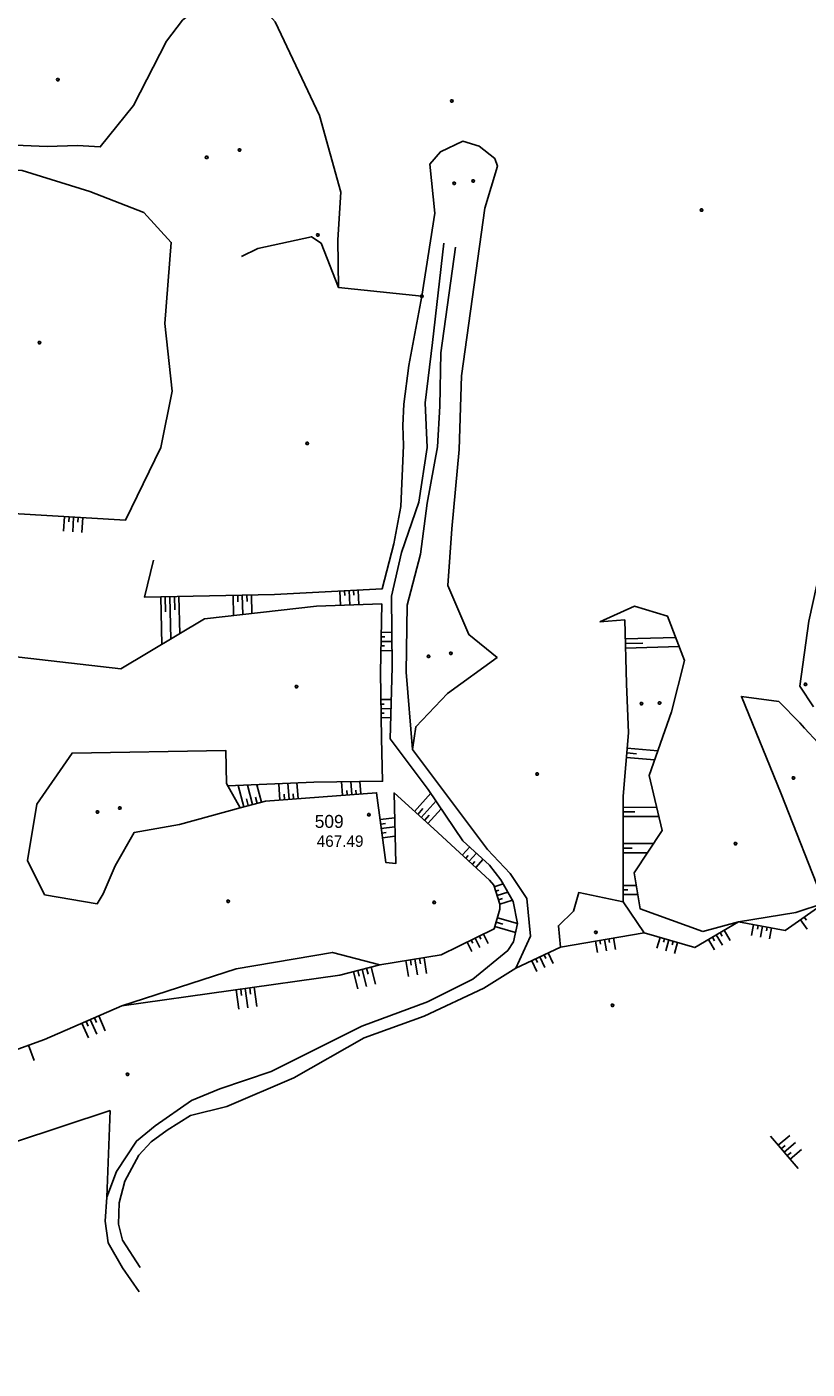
# Model space of a CAD drawing. Extents: x -664960 to -662754, y -993849 to -991145.
# Drawn here: x -664357.5 to -664152.5, y -993457.1 to -993104.4 of the extents above; entities that cross this region are included whole.
import ezdxf

# ---------------------------------------------------------------- set-up
doc = ezdxf.new("R2010")
doc.units = 0
for name, color, linetype in [('Vrstva 1', 7, 'Continuous'), ('Vrstva 12', 7, 'Continuous'), ('Vrstva 13', 7, 'Continuous'), ('Vrstva 18', 7, 'Continuous'), ('Vrstva 27', 7, 'Continuous'), ('Vrstva 63', 7, 'Continuous'), ('Vrstva 8', 7, 'Continuous')]:
    doc.layers.add(name, color=color, linetype=linetype)

msp = doc.modelspace()

# ---------------------------------------------------------------- linework, layer by layer
at = {"layer": 'Vrstva 12'}
msp.add_lwpolyline([(-664301.104, -993164.69), (-664296.848, -993162.65), (-664282.753, -993159.535), (-664280.216, -993161.227), (-664275.632, -993172.854), (-664253.73, -993175.159), (-664257.123, -993193.361), (-664258.44, -993203.55), (-664258.71, -993209.141), (-664258.56, -993214.4), (-664259.22, -993230.41), (-664261.06, -993240.18), (-664264.14, -993252.02), (-664292.45, -993253.54), (-664326.59, -993254.23), (-664324.275, -993244.488)], dxfattribs=at)
at = {"layer": 'Vrstva 13'}
for points in [[(-664349.185, -993117.942), (-664349.005, -993118.242), (-664349.185, -993118.542), (-664349.545, -993118.542), (-664349.725, -993118.242), (-664349.545, -993117.942), (-664349.185, -993117.942)], [(-664310.087, -993138.378), (-664309.907, -993138.678), (-664310.087, -993138.978), (-664310.447, -993138.978), (-664310.627, -993138.678), (-664310.447, -993138.378), (-664310.087, -993138.378)], [(-664301.437, -993136.432), (-664301.257, -993136.732), (-664301.437, -993137.032), (-664301.797, -993137.032), (-664301.977, -993136.732), (-664301.797, -993136.432), (-664301.437, -993136.432)], [(-664245.039, -993145.177), (-664244.859, -993145.477), (-664245.039, -993145.777), (-664245.399, -993145.777), (-664245.579, -993145.477), (-664245.399, -993145.177), (-664245.039, -993145.177)], [(-664240.048, -993144.566), (-664239.868, -993144.866), (-664240.048, -993145.166), (-664240.408, -993145.166), (-664240.588, -993144.866), (-664240.408, -993144.566), (-664240.048, -993144.566)], [(-664180.033, -993152.234), (-664179.853, -993152.534), (-664180.033, -993152.834), (-664180.393, -993152.834), (-664180.573, -993152.534), (-664180.393, -993152.234), (-664180.033, -993152.234)], [(-664354.029, -993187.034), (-664353.849, -993187.334), (-664354.029, -993187.634), (-664354.389, -993187.634), (-664354.569, -993187.334), (-664354.389, -993187.034), (-664354.029, -993187.034)], [(-664283.665, -993213.532), (-664283.485, -993213.832), (-664283.665, -993214.132), (-664284.025, -993214.132), (-664284.205, -993213.832), (-664284.025, -993213.532), (-664283.665, -993213.532)], [(-664251.766, -993269.477), (-664251.586, -993269.777), (-664251.766, -993270.077), (-664252.126, -993270.077), (-664252.306, -993269.777), (-664252.126, -993269.477), (-664251.766, -993269.477)], [(-664245.907, -993268.663), (-664245.727, -993268.963), (-664245.907, -993269.263), (-664246.267, -993269.263), (-664246.447, -993268.963), (-664246.267, -993268.663), (-664245.907, -993268.663)], [(-664286.486, -993277.411), (-664286.306, -993277.711), (-664286.486, -993278.011), (-664286.846, -993278.011), (-664287.026, -993277.711), (-664286.846, -993277.411), (-664286.486, -993277.411)], [(-664195.842, -993281.895), (-664195.662, -993282.195), (-664195.842, -993282.495), (-664196.202, -993282.495), (-664196.382, -993282.195), (-664196.202, -993281.895), (-664195.842, -993281.895)], [(-664191.054, -993281.734), (-664190.874, -993282.034), (-664191.054, -993282.334), (-664191.414, -993282.334), (-664191.594, -993282.034), (-664191.414, -993281.734), (-664191.054, -993281.734)], [(-664223.263, -993300.425), (-664223.083, -993300.725), (-664223.263, -993301.025), (-664223.623, -993301.025), (-664223.803, -993300.725), (-664223.623, -993300.425), (-664223.263, -993300.425)], [(-664155.894, -993301.408), (-664155.714, -993301.708), (-664155.894, -993302.008), (-664156.254, -993302.008), (-664156.434, -993301.708), (-664156.254, -993301.408), (-664155.894, -993301.408)], [(-664338.783, -993310.368), (-664338.603, -993310.668), (-664338.783, -993310.968), (-664339.143, -993310.968), (-664339.323, -993310.668), (-664339.143, -993310.368), (-664338.783, -993310.368)], [(-664332.924, -993309.351), (-664332.744, -993309.651), (-664332.924, -993309.951), (-664333.284, -993309.951), (-664333.464, -993309.651), (-664333.284, -993309.351), (-664332.924, -993309.351)], [(-664171.123, -993318.678), (-664170.943, -993318.978), (-664171.123, -993319.278), (-664171.483, -993319.278), (-664171.663, -993318.978), (-664171.483, -993318.678), (-664171.123, -993318.678)], [(-664304.443, -993333.814), (-664304.263, -993334.114), (-664304.443, -993334.414), (-664304.803, -993334.414), (-664304.983, -993334.114), (-664304.803, -993333.814), (-664304.443, -993333.814)], [(-664250.302, -993334.119), (-664250.122, -993334.419), (-664250.302, -993334.719), (-664250.662, -993334.719), (-664250.842, -993334.419), (-664250.662, -993334.119), (-664250.302, -993334.119)], [(-664207.812, -993341.974), (-664207.632, -993342.274), (-664207.812, -993342.574), (-664208.172, -993342.574), (-664208.352, -993342.274), (-664208.172, -993341.974), (-664207.812, -993341.974)], [(-664203.444, -993361.142), (-664203.264, -993361.442), (-664203.444, -993361.742), (-664203.804, -993361.742), (-664203.984, -993361.442), (-664203.804, -993361.142), (-664203.444, -993361.142)], [(-664330.878, -993379.271), (-664330.698, -993379.571), (-664330.878, -993379.871), (-664331.238, -993379.871), (-664331.418, -993379.571), (-664331.238, -993379.271), (-664330.878, -993379.271)]]:
    msp.add_lwpolyline(points, dxfattribs=at)
at = {"layer": 'Vrstva 18'}
for points in [[(-664245.69, -993123.56), (-664245.51, -993123.86), (-664245.69, -993124.16), (-664246.05, -993124.16), (-664246.23, -993123.86), (-664246.05, -993123.56), (-664245.69, -993123.56)], [(-664280.891, -993158.738), (-664280.711, -993159.038), (-664280.891, -993159.338), (-664281.251, -993159.338), (-664281.431, -993159.038), (-664281.251, -993158.738), (-664280.891, -993158.738)], [(-664253.55, -993174.859), (-664253.37, -993175.159), (-664253.55, -993175.459), (-664253.91, -993175.459), (-664254.09, -993175.159), (-664253.91, -993174.859), (-664253.55, -993174.859)]]:
    msp.add_lwpolyline(points, dxfattribs=at)
at = {"layer": 'Vrstva 27'}
for points in [[(-664247.94, -993161.23), (-664250.96, -993187.28), (-664252.81, -993203.17), (-664252.29, -993214.93), (-664254.49, -993229.29), (-664259.07, -993242.45), (-664261.72, -993253.99), (-664261.52, -993272.6), (-664262.05, -993291.42), (-664252.07, -993304.72), (-664242.91, -993318.25), (-664235.92, -993324.61), (-664232.93, -993328.5), (-664229.68, -993334.2), (-664228.56, -993340.01), (-664229.65, -993344.75)], [(-664229.01, -993351.74), (-664225.2, -993343.3), (-664226.12, -993333.39), (-664230.54, -993326.85), (-664236.51, -993320.52), (-664256.21, -993294.26), (-664257.8, -993273.94), (-664257.56, -993256.29), (-664254.09, -993242.89), (-664252.3, -993229.52), (-664249.58, -993214.77), (-664249, -993204.08), (-664248.69, -993190.01), (-664244.88, -993162.3)], [(-664314.24, -993386.46), (-664306.776, -993383.379), (-664293.287, -993378.845), (-664269.506, -993366.909), (-664252.229, -993360.577), (-664240.3, -993354.597), (-664231.144, -993347.069), (-664229.65, -993344.75)], [(-664229.01, -993351.74), (-664237.453, -993356.985), (-664253.09, -993364.277), (-664268.874, -993370.048), (-664287.316, -993380.536), (-664304.993, -993388.063), (-664314.496, -993390.431)], [(-664328.001, -993436.737), (-664332.398, -993430.456), (-664336.113, -993423.883), (-664336.904, -993418.153), (-664336.457, -993411.901), (-664333.964, -993405.119), (-664328.665, -993397.156), (-664323.816, -993393.158), (-664314.24, -993386.46)], [(-664314.496, -993390.431), (-664320.627, -993394.289), (-664324.839, -993397.33), (-664328.059, -993400.797), (-664331.791, -993407.686), (-664333.292, -993413.327), (-664333.438, -993418.976), (-664332.402, -993423.206), (-664327.759, -993430.373)]]:
    msp.add_lwpolyline(points, dxfattribs=at)
at = {"layer": 'Vrstva 63'}
for p, q in [((-664347.612, -993233.027), (-664347.842, -993236.924)), ((-664346.414, -993233.098), (-664346.491, -993234.395)), ((-664345.217, -993233.168), (-664345.446, -993237.065)), ((-664344.019, -993233.239), (-664344.095, -993234.537)), ((-664342.821, -993233.31), (-664343.05, -993237.207)), ((-664322.339, -993254.144), (-664322.086, -993266.678)), ((-664321.14, -993254.12), (-664321.06, -993258.066)), ((-664319.94, -993254.096), (-664319.714, -993265.262)), ((-664318.74, -993254.071), (-664318.669, -993257.562)), ((-664317.54, -993254.047), (-664317.342, -993263.847)), ((-664303.295, -993253.759), (-664303.188, -993259.073)), ((-664302.096, -993253.735), (-664302.061, -993255.466)), ((-664300.896, -993253.711), (-664300.793, -993258.797)), ((-664299.696, -993253.686), (-664299.663, -993255.342)), ((-664298.496, -993253.662), (-664298.398, -993258.521)), ((-664275.258, -993252.617), (-664275.057, -993256.362)), ((-664274.06, -993252.553), (-664273.993, -993253.808)), ((-664272.862, -993252.488), (-664272.658, -993256.286)), ((-664271.663, -993252.424), (-664271.595, -993253.697)), ((-664270.465, -993252.36), (-664270.258, -993256.21)), ((-664264.428, -993265.833), (-664261.592, -993265.896)), ((-664264.401, -993264.633), (-664263.47, -993264.654)), ((-664264.375, -993263.433), (-664261.618, -993263.495)), ((-664200.25, -993265.211), (-664187.006, -993264.841)), ((-664264.481, -993268.232), (-664261.566, -993268.297)), ((-664264.454, -993267.033), (-664263.497, -993267.054)), ((-664200.217, -993266.41), (-664195.667, -993266.283)), ((-664200.183, -993267.61), (-664186.102, -993267.217)), ((-664264.507, -993281.124), (-664261.759, -993281.084)), ((-664264.49, -993282.324), (-664263.592, -993282.311)), ((-664264.473, -993283.523), (-664261.827, -993283.485)), ((-664264.455, -993284.723), (-664263.591, -993284.711)), ((-664264.438, -993285.923), (-664261.894, -993285.886)), ((-664199.771, -993293.944), (-664191.737, -993294.596)), ((-664199.965, -993296.336), (-664192.569, -993296.937)), ((-664199.868, -993295.14), (-664197.299, -993295.349)), ((-664300.505, -993309.302), (-664301.958, -993303.718)), ((-664298.182, -993308.698), (-664299.506, -993303.608)), ((-664295.859, -993308.093), (-664297.055, -993303.499)), ((-664291.006, -993307.526), (-664291.329, -993303.243)), ((-664288.613, -993307.345), (-664288.931, -993303.136)), ((-664286.22, -993307.165), (-664286.532, -993303.029)), ((-664274.55, -993306.285), (-664274.819, -993302.73)), ((-664272.157, -993306.104), (-664272.414, -993302.696)), ((-664269.764, -993305.923), (-664270.01, -993302.663)), ((-664299.344, -993309), (-664299.806, -993307.223)), ((-664297.021, -993308.396), (-664297.44, -993306.783)), ((-664289.81, -993307.436), (-664289.916, -993306.022)), ((-664287.416, -993307.255), (-664287.521, -993305.866)), ((-664273.354, -993306.194), (-664273.441, -993305.035)), ((-664270.961, -993306.014), (-664271.044, -993304.903)), ((-664255.673, -993310.5), (-664251.384, -993305.733)), ((-664253.889, -993312.105), (-664249.998, -993307.781)), ((-664254.781, -993311.303), (-664253.419, -993309.789)), ((-664252.997, -993312.908), (-664251.767, -993311.542)), ((-664252.105, -993313.711), (-664248.612, -993309.828)), ((-664200.803, -993311.844), (-664191.47, -993311.867)), ((-664200.8, -993310.644), (-664197.788, -993310.651)), ((-664200.797, -993309.444), (-664192.038, -993309.466)), ((-664264.688, -993312.669), (-664260.862, -993312.169)), ((-664264.533, -993313.859), (-664263.3, -993313.698)), ((-664264.377, -993315.049), (-664260.799, -993314.581)), ((-664264.222, -993316.238), (-664263.072, -993316.088)), ((-664264.067, -993317.428), (-664260.736, -993316.993)), ((-664200.821, -993318.965), (-664192.884, -993318.985)), ((-664243.079, -993321.969), (-664241.142, -993319.859)), ((-664242.195, -993322.78), (-664241.549, -993322.076)), ((-664241.311, -993323.592), (-664239.367, -993321.474)), ((-664200.828, -993321.365), (-664194.447, -993321.381)), ((-664200.824, -993320.165), (-664198.44, -993320.171)), ((-664240.427, -993324.404), (-664239.779, -993323.697)), ((-664239.543, -993325.215), (-664237.592, -993323.089)), ((-664234.692, -993330.361), (-664232.315, -993329.578)), ((-664234.316, -993331.501), (-664233.448, -993331.215)), ((-664233.941, -993332.64), (-664231.102, -993331.706)), ((-664200.855, -993332.364), (-664196.972, -993332.374)), ((-664200.852, -993331.164), (-664199.626, -993331.167)), ((-664200.849, -993329.964), (-664197.368, -993329.973)), ((-664233.565, -993333.78), (-664232.543, -993333.444)), ((-664233.19, -993334.92), (-664229.889, -993333.833)), ((-664195.34, -993342.39), (-664200.86, -993334.24)), ((-664234.208, -993339.641), (-664232.417, -993340.154)), ((-664233.878, -993338.488), (-664228.56, -993340.01)), ((-664154.227, -993338.992), (-664152.511, -993341.431)), ((-664153.245, -993338.302), (-664152.674, -993339.114)), ((-664238.592, -993343.284), (-664238.192, -993344.093)), ((-664237.516, -993342.752), (-664236.316, -993345.181)), ((-664234.538, -993340.795), (-664229.099, -993342.352)), ((-664191.117, -993343.622), (-664191.946, -993346.465)), ((-664177.386, -993343.577), (-664176.85, -993344.484)), ((-664176.353, -993342.966), (-664174.742, -993345.688)), ((-664175.321, -993342.355), (-664174.784, -993343.261)), ((-664174.288, -993341.744), (-664172.677, -993344.465)), ((-664166.545, -993340.231), (-664167.092, -993343.131)), ((-664165.366, -993340.454), (-664165.548, -993341.419)), ((-664164.187, -993340.676), (-664164.733, -993343.575)), ((-664163.008, -993340.898), (-664163.189, -993341.864)), ((-664161.828, -993341.12), (-664162.375, -993344.02)), ((-664241.819, -993344.879), (-664240.619, -993347.308)), ((-664240.744, -993344.347), (-664240.344, -993345.156)), ((-664239.668, -993343.815), (-664238.467, -993346.245)), ((-664208.117, -993344.582), (-664207.602, -993347.581)), ((-664206.934, -993344.379), (-664206.763, -993345.378)), ((-664205.751, -993344.177), (-664205.237, -993347.175)), ((-664204.569, -993343.974), (-664204.397, -993344.972)), ((-664203.386, -993343.771), (-664202.871, -993346.769)), ((-664189.965, -993343.958), (-664190.241, -993344.905)), ((-664188.813, -993344.294), (-664189.642, -993347.137)), ((-664187.661, -993344.63), (-664187.937, -993345.577)), ((-664186.509, -993344.966), (-664187.338, -993347.809)), ((-664178.419, -993344.188), (-664176.808, -993346.91)), ((-664257.889, -993349.73), (-664257.225, -993353.863)), ((-664256.704, -993349.54), (-664256.483, -993350.916)), ((-664255.52, -993349.349), (-664254.855, -993353.482)), ((-664254.335, -993349.159), (-664254.114, -993350.535)), ((-664253.15, -993348.968), (-664252.486, -993353.101)), ((-664224.86, -993349.761), (-664223.529, -993352.55)), ((-664223.776, -993349.244), (-664223.333, -993350.173)), ((-664222.693, -993348.727), (-664221.363, -993351.517)), ((-664221.61, -993348.211), (-664221.167, -993349.14)), ((-664220.527, -993347.694), (-664219.197, -993350.484)), ((-664271.721, -993352.647), (-664270.553, -993357.141)), ((-664270.56, -993352.345), (-664270.171, -993353.842)), ((-664269.398, -993352.043), (-664268.23, -993356.537)), ((-664268.237, -993351.742), (-664267.848, -993353.238)), ((-664267.076, -993351.44), (-664265.908, -993355.933)), ((-664302.509, -993357.383), (-664301.799, -993362.467)), ((-664301.321, -993357.217), (-664301.084, -993358.91)), ((-664300.133, -993357.05), (-664299.422, -993362.134)), ((-664298.944, -993356.884), (-664298.707, -993358.577)), ((-664297.756, -993356.718), (-664297.045, -993361.802)), ((-664339.74, -993364.718), (-664339.176, -993366.014)), ((-664338.64, -993364.239), (-664336.946, -993368.13)), ((-664343.041, -993366.155), (-664341.347, -993370.046)), ((-664341.94, -993365.676), (-664341.377, -993366.972)), ((-664340.84, -993365.197), (-664339.147, -993369.088)), ((-664357.079, -993371.943), (-664355.621, -993376.002)), ((-664336.457, -993411.901), (-664335.62, -993389.11)), ((-664162.07, -993395.87), (-664154.81, -993404.35)), ((-664160.05, -993398.23), (-664157.053, -993395.664)), ((-664159.269, -993399.141), (-664158.271, -993398.287)), ((-664158.489, -993400.053), (-664155.492, -993397.487)), ((-664156.928, -993401.876), (-664153.931, -993399.31)), ((-664157.709, -993400.964), (-664156.711, -993400.11))]:
    msp.add_line(p, q, dxfattribs=at)
for points in [[(-664130.678, -993066.532), (-664125.037, -993071.808), (-664119.18, -993086.85), (-664114.57, -993099.61), (-664113.25, -993107.22), (-664114.08, -993121.25), (-664117.42, -993139.12), (-664123.32, -993165.24), (-664133.21, -993201.92), (-664135.82, -993209.56), (-664144.89, -993233.81), (-664149, -993246.64), (-664152, -993260.56), (-664154.41, -993277.57), (-664150.84, -993283.04)], [(-664275.632, -993172.854), (-664275.778, -993160.323), (-664275.008, -993147.824), (-664280.601, -993127.698), (-664292.22, -993103.072), (-664298.125, -993096.408), (-664305.565, -993094.546), (-664309.784, -993096.905), (-664316.613, -993102.586), (-664320.825, -993108.164), (-664329.492, -993125.07)], [(-664329.492, -993125.07), (-664338.22, -993135.913), (-664344.188, -993135.516), (-664352.168, -993135.839), (-664373.332, -993134.916), (-664371.432, -993107.401), (-664375.093, -993105.807), (-664379.258, -993129.736), (-664380.209, -993139.827), (-664376.739, -993140.978), (-664358.74, -993142.14), (-664340.989, -993147.64), (-664326.791, -993153.115), (-664319.57, -993161.021), (-664321.295, -993182.296), (-664319.288, -993200.14), (-664322.318, -993214.912), (-664331.554, -993233.974), (-664361.096, -993232.232), (-664391.879, -993227.408), (-664388.495, -993205.096), (-664387.402, -993190.563)], [(-664256.21, -993294.26), (-664255.34, -993288.29), (-664246.94, -993279.56), (-664233.96, -993270.06), (-664241.4, -993264.05), (-664246.87, -993251.13), (-664245.81, -993236.26), (-664243.93, -993215.41), (-664243.28, -993196.04), (-664237.18, -993151.98), (-664233.86, -993141), (-664234.557, -993139.004), (-664238.665, -993135.729), (-664242.98, -993134.437), (-664248.834, -993137.205), (-664251.627, -993140.42), (-664250.338, -993153.371), (-664253.73, -993175.159)], [(-664264.21, -993256.02), (-664281.36, -993256.56), (-664310.81, -993259.95), (-664332.8, -993273.07), (-664359.49, -993269.96), (-664387.72, -993266.77), (-664399.42, -993269.98), (-664408.62, -993286.89), (-664411.21, -993295.98)], [(-664264.21, -993256.02), (-664264.61, -993274.04), (-664264.36, -993291.31), (-664264.02, -993302.58), (-664282.07, -993302.83), (-664304.689, -993303.839)], [(-664206.94, -993260.69), (-664197.87, -993256.62), (-664189.16, -993259.18), (-664184.7, -993270.9), (-664188.09, -993284.33), (-664194.03, -993301.05), (-664190.61, -993315.5), (-664197.91, -993326.69), (-664196.35, -993336.14), (-664179.92, -993342.03)], [(-664206.94, -993260.69), (-664200.39, -993260.21), (-664199.92, -993277.04), (-664199.44, -993289.87), (-664200.79, -993306.5), (-664200.86, -993334.24), (-664212.49, -993331.85), (-664213.84, -993336.76), (-664217.83, -993340.57), (-664217.31, -993346.16)], [(-664152.74, -993276.83), (-664152.56, -993277.13), (-664152.74, -993277.43), (-664153.1, -993277.43), (-664153.28, -993277.13), (-664153.1, -993276.83), (-664152.74, -993276.83)], [(-664149.55, -993292.53), (-664153.17, -993288.63), (-664154.4, -993287.22), (-664159.92, -993281.66), (-664169.74, -993280.29), (-664159.28, -993305.93), (-664148.01, -993334.62), (-664155.45, -993337.05), (-664170.48, -993339.49), (-664179.92, -993342.03)], [(-664235.9, -993328.56), (-664250.55, -993315.11), (-664261.03, -993305.68), (-664260.55, -993324.18), (-664263.22, -993323.91), (-664265.61, -993305.61), (-664294.77, -993307.81), (-664301.42, -993309.54), (-664317.36, -993313.92), (-664329.29, -993316.02), (-664334.28, -993324.86), (-664337.45, -993332.18), (-664339.01, -993334.77), (-664352.87, -993332.42), (-664357.31, -993323.45), (-664354.87, -993308.63), (-664345.62, -993295.2), (-664305.21, -993294.53), (-664305.05, -993303.21), (-664301.42, -993309.54)], [(-664412.65, -993303.65), (-664413.05, -993321.45), (-664418.01, -993339.7), (-664421.9, -993357.53), (-664430.97, -993377.9), (-664430.06, -993383.38), (-664427.19, -993384.76), (-664420.39, -993385.34), (-664400.61, -993383.3), (-664366.95, -993375.49), (-664352.84, -993370.42), (-664332.53, -993361.58), (-664302.52, -993351.87), (-664277.21, -993347.57), (-664264.73, -993350.83), (-664248.62, -993348.24), (-664234.7, -993341.36), (-664233.22, -993336.19), (-664233.19, -993334.92), (-664234.84, -993329.91), (-664235.9, -993328.56)], [(-664148.01, -993334.62), (-664158.22, -993341.8), (-664170.48, -993339.49), (-664181.97, -993346.29), (-664195.34, -993342.39)], [(-664195.34, -993342.39), (-664217.31, -993346.16), (-664229.01, -993351.74)], [(-664332.53, -993361.58), (-664275.31, -993353.58), (-664264.73, -993350.83)], [(-664335.62, -993389.11), (-664373.51, -993401.67), (-664385.42, -993407.96), (-664399.13, -993414.74), (-664532.002, -993457.062)]]:
    msp.add_lwpolyline(points, dxfattribs=at)
at = {"layer": 'Vrstva 8'}
msp.add_lwpolyline([(-664267.44, -993311.09), (-664267.26, -993311.39), (-664267.44, -993311.69), (-664267.8, -993311.69), (-664267.98, -993311.39), (-664267.8, -993311.09), (-664267.44, -993311.09)], dxfattribs=at)

# ---------------------------------------------------------------- texts
at = {"layer": 'Vrstva 1'}
msp.add_text('509', height=3.4, dxfattribs=at).set_placement((-664281.857, -993314.848))
at = {"layer": 'Vrstva 63'}
msp.add_text('467.49', height=3, dxfattribs=at).set_placement((-664281.333, -993319.828))

doc.saveas('drawing.dxf')
